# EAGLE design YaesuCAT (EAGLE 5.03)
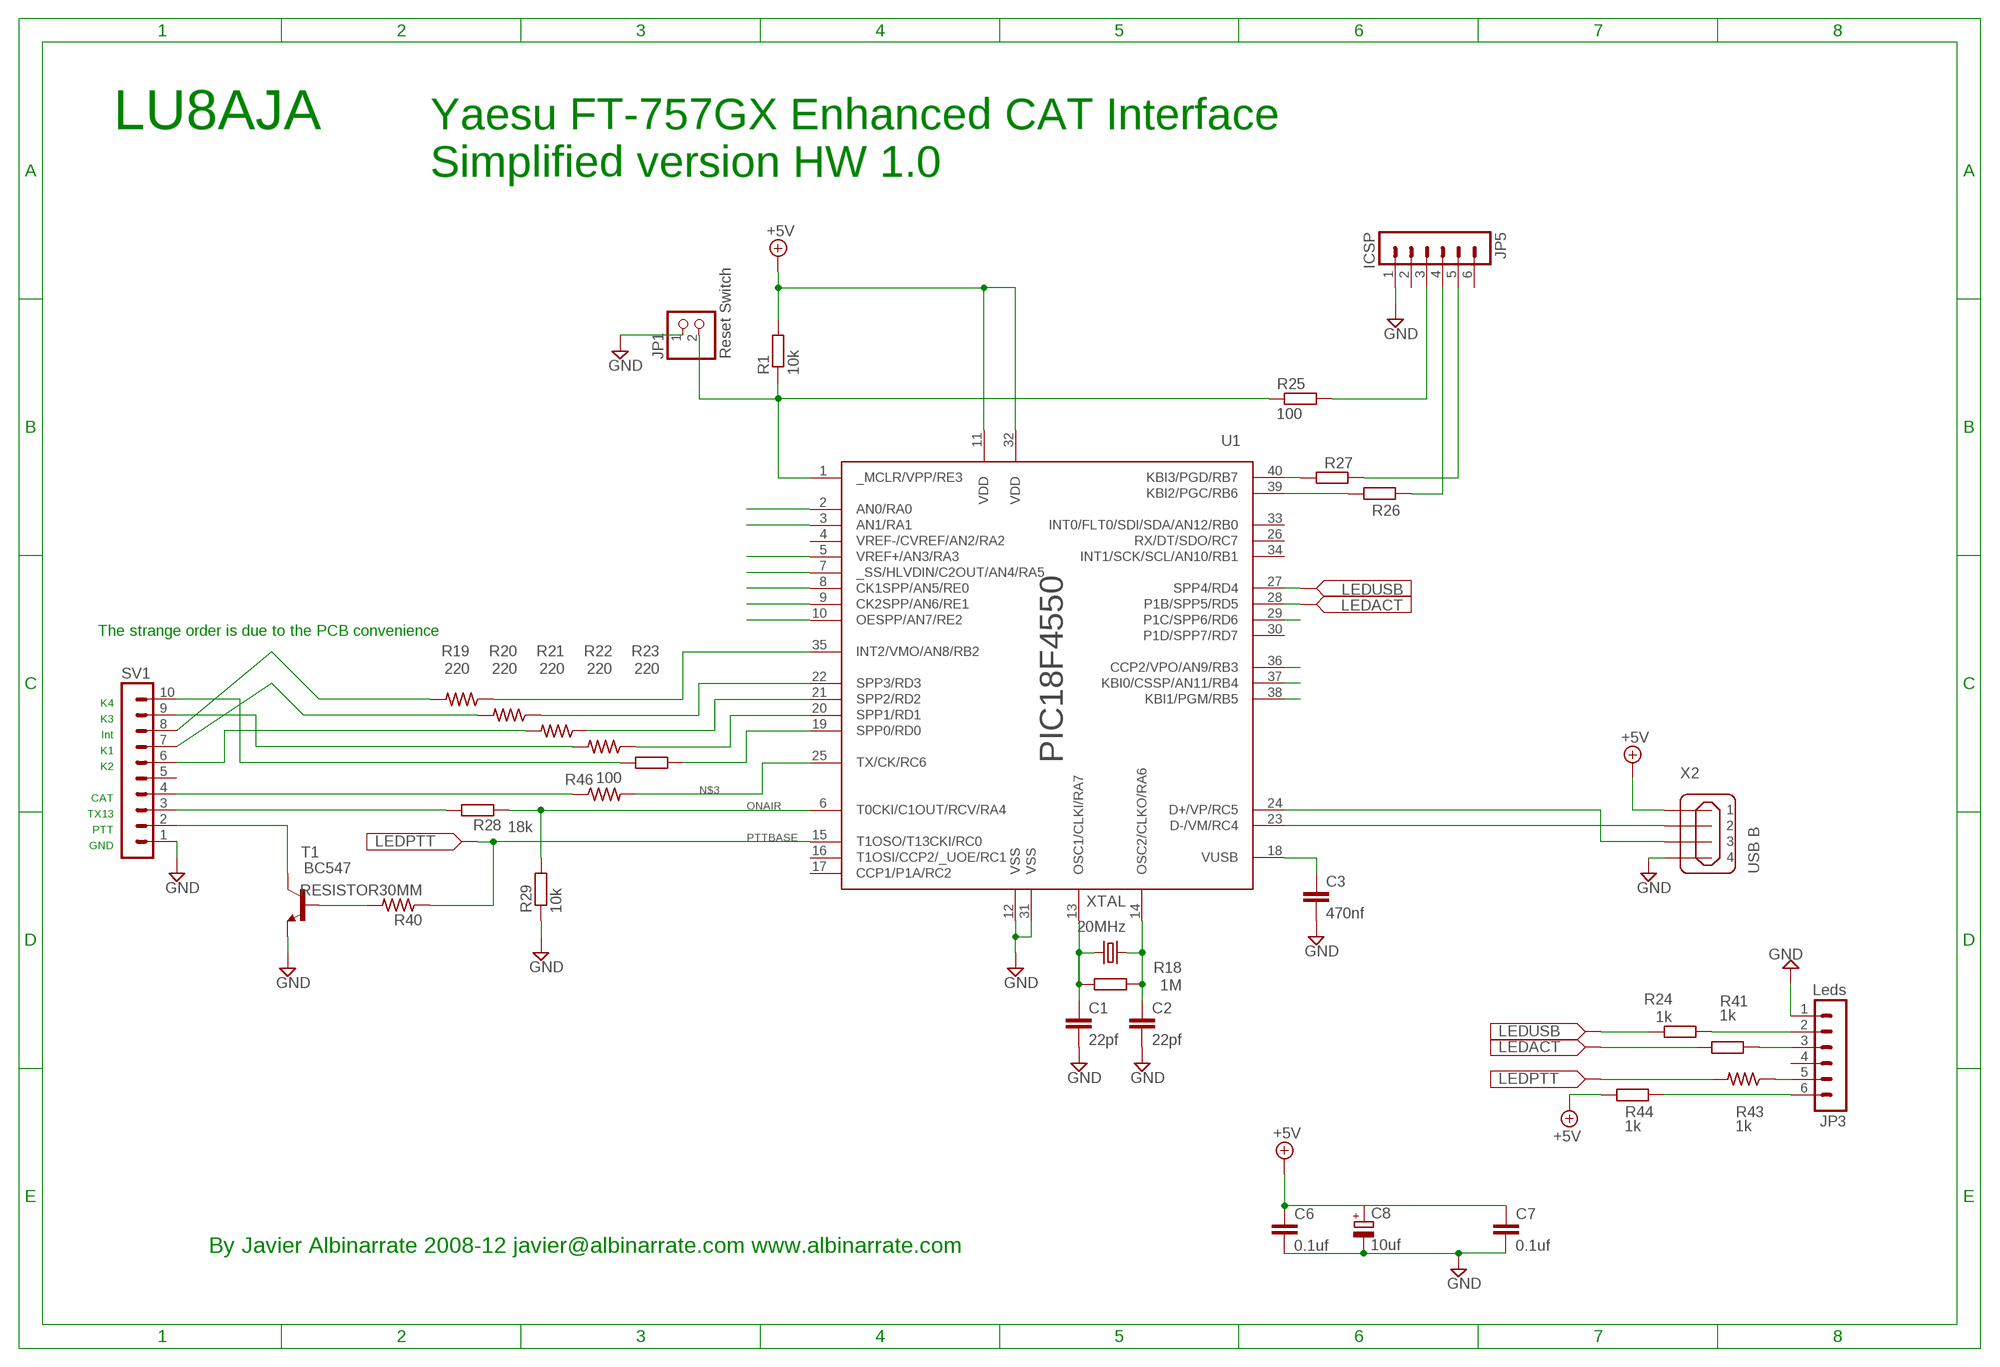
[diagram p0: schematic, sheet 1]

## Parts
C1  22pf  C-EU050-035X075  [C050-035X075]
C2  22pf  C-EU050-035X075  [C050-035X075]
C3  470nf  C-EU050-035X075  [C050-035X075]
C6  0.1uf  C-EU050-035X075  [C050-035X075]
C7  0.1uf  C-EU050-035X075  [C050-035X075]
C8  10uf  CPOL-EUE5-10.5  [E5-10,5]
JP1  Reset Switch  PINHD-1X2  [1X02]
JP3  Leds  MA06-1  [MA06-1]
JP5  ICSP  MA06-1  [MA06-1]
R1  10k  R-EU_0207/10  [0207/10]
R18  1M  R-EU_0207/10  [0207/10]
R19  220  R-US_0207/10  [0207/10]
R20  220  R-US_0207/10  [0207/10]
R21  220  R-US_0207/10  [0207/10]
R22  220  R-US_0207/10  [0207/10]
R23  220  R-EU_0207/10  [0207/10]
R24  1k  R-EU_0207/10  [0207/10]
R25  100  R-EU_0207/10  [0207/10]
R26  R-EU_0207/10  [0207/10]
R27  R-EU_0207/10  [0207/10]
R28  18k  R-EU_0207/10  [0207/10]
R29  10k  R-EU_0207/10  [0207/10]
R40  RESISTOR30MM  [R207/30MM]
R41  1k  R-EU_0207/10  [0207/10]
R43  1k  RESISTOR20MM  [R207/20MM]
R44  1k  R-EU_0207/10  [0207/10]
R46  100  R-US_0207/10  [0207/10]
SV1  MA10-1  [MA10-1]
T1  BC547  [TO92]
U1  PIC18F4550  [DIP40]
X2  USB B  MINI-USB_SHIELD4P-85-32004-00X  [85-32004-00X]
XTAL  20MHz  CRYSTALHC49U70  [HC49U70]

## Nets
+5V: C6.1 C7.1 C8.+ R1.2 R44.2 U1.11(VDD) U1.32(VDD) X2.1
AN0: U1.2(AN0/RA0)
AN1: U1.3(AN1/RA1)
AN3: U1.5(VREF+/AN3/RA3)
AN4: U1.7(_SS/HLVDIN/C2OUT/AN4/RA5)
AN5: U1.8(CK1SPP/AN5/RE0)
AN6: U1.9(CK2SPP/AN6/RE1)
AN7: U1.10(OESPP/AN7/RE2)
AN9: U1.36(CCP2/VPO/AN9/RB3)
D+: U1.24(D+/VP/RC5) X2.3
D-: U1.23(D-/VM/RC4) X2.2
GND: C1.2 C2.2 C3.2 C6.2 C7.2 C8.- JP1.1 JP3.1 JP5.1 R29.1 SV1.1 T1.1(E) U1.12(VSS) U1.31(VSS) X2.4
INT: R19.1 U1.35(INT2/VMO/AN8/RB2)
LEDACT: R41.1 U1.28(P1B/SPP5/RD5)
LEDUSB: R24.2 U1.27(SPP4/RD4)
N$1: JP1.2 R1.1 R25.1 U1.1(_MCLR/VPP/RE3)
N$2: JP5.4 R26.1
N$3: R46.2 U1.25(TX/CK/RC6)
N$4: R28.2 SV1.3
N$5: SV1.2 T1.3(C)
N$6: R46.1 SV1.4
N$7: R23.2 SV1.10
N$8: R22.2 SV1.9
N$9: R21.2 SV1.6
N$10: R20.1 U1.22(SPP3/RD3)
N$11: R27.2 U1.40(KBI3/PGD/RB7)
N$12: R26.2 U1.39(KBI2/PGC/RB6)
N$13: R21.1 U1.21(SPP2/RD2)
N$14: JP5.5 R27.1
N$15: R20.2 SV1.7
N$16: R19.2 SV1.8
N$20: JP5.3 R25.2
N$22: JP3.2 R24.1
N$23: JP3.3 R41.2
N$25: JP3.5 R43.P$1
N$30: JP3.6 R44.1
N$34: C1.1 R18.2 U1.13(OSC1/CLKI/RA7) XTAL.2
N$35: C2.1 R18.1 U1.14(OSC2/CLKO/RA6) XTAL.1
N$37: C3.1 U1.18(VUSB)
N$49: R40.P$2 T1.2(B)
ONAIR: R28.1 R29.2 U1.6(T0CKI/C1OUT/RCV/RA4)
PTTBASE: R40.P$1 R43.P$2 U1.15(T1OSO/T13CKI/RC0) ; supply symbol labelled LEDPTT
RD0: R23.1 U1.19(SPP0/RD0)
RD1: R22.1 U1.20(SPP1/RD1)
RESET: U1.29(P1C/SPP6/RD6)
START: U1.38(KBI1/PGM/RB5)
THRU: U1.37(KBI0/CSSP/AN11/RB4)
Unconnected: JP3.4 JP5.2 JP5.6 SV1.5 U1.4(VREF-/CVREF/AN2/RA2) U1.16(T1OSI/CCP2/_UOE/RC1) U1.17(CCP1/P1A/RC2) U1.26(RX/DT/SDO/RC7) U1.30(P1D/SPP7/RD7) U1.33(INT0/FLT0/SDI/SDA/AN12/RB0) U1.34(INT1/SCK/SCL/AN10/RB1) X2.M1(S1) X2.M2(S2)

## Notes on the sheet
- LU8AJA | Yaesu FT-757GX Enhanced CAT Interface
- Simplified version HW 1.0
- The strange order is due to the PCB convenience
- K4
- K3
- Int
- K1
- K2
- CAT
- TX13
- PTT
- GND
- By Javier Albinarrate 2008-12 javier@albinarrate.com www.albinarrate.com

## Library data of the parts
C1-C3 C6 C7 = resistor:C-EU: CAPACITOR, European symbol
C8 = resistor:CPOL-EU: POLARIZED CAPACITOR, European symbol
JP1 = pinhead:PINHD-1X2: PIN HEADER
JP3 JP5 = con-lstb:MA06-1: PIN HEADER
R1 R18 R23-R29 R41 R44 = resistor:R-EU_: RESISTOR, European symbol
R19-R22 R46 = resistor:R-US_: RESISTOR, American symbol
R40 R43 = components:RESISTOR
SV1 = con-lstb:MA10-1: PIN HEADER
T1 = transistor:BC547: NPN TRANSISTOR
U1 = components:PIC18F4550: PIC18F4550 DIP-40 Specially arranged for schematics for the Yaesu FT-757GX Enhanced CAT interface schematics.
X2 = con-cypressindustries:MINI-USB_SHIELD4P-: MINI USB 4 Pol. Source: www.cypressindustries.com
XTAL = crystal:CRYSTAL: CRYSTAL

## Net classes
0 default: width 0.508 mm, drill 0.127 mm, clearance 0.381 mm

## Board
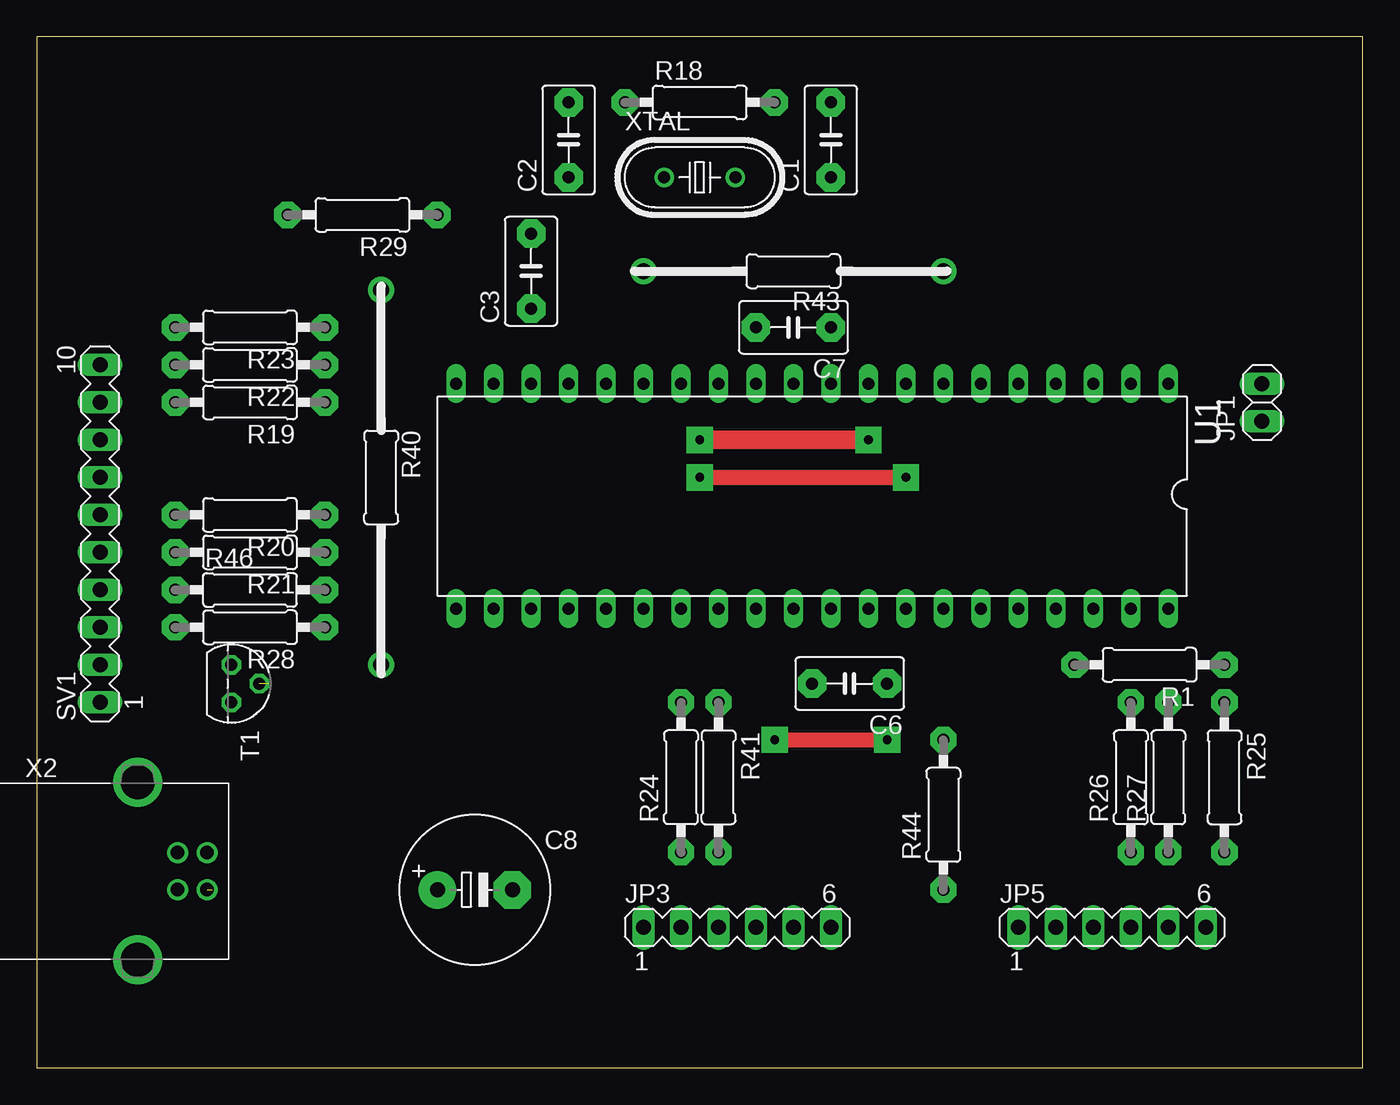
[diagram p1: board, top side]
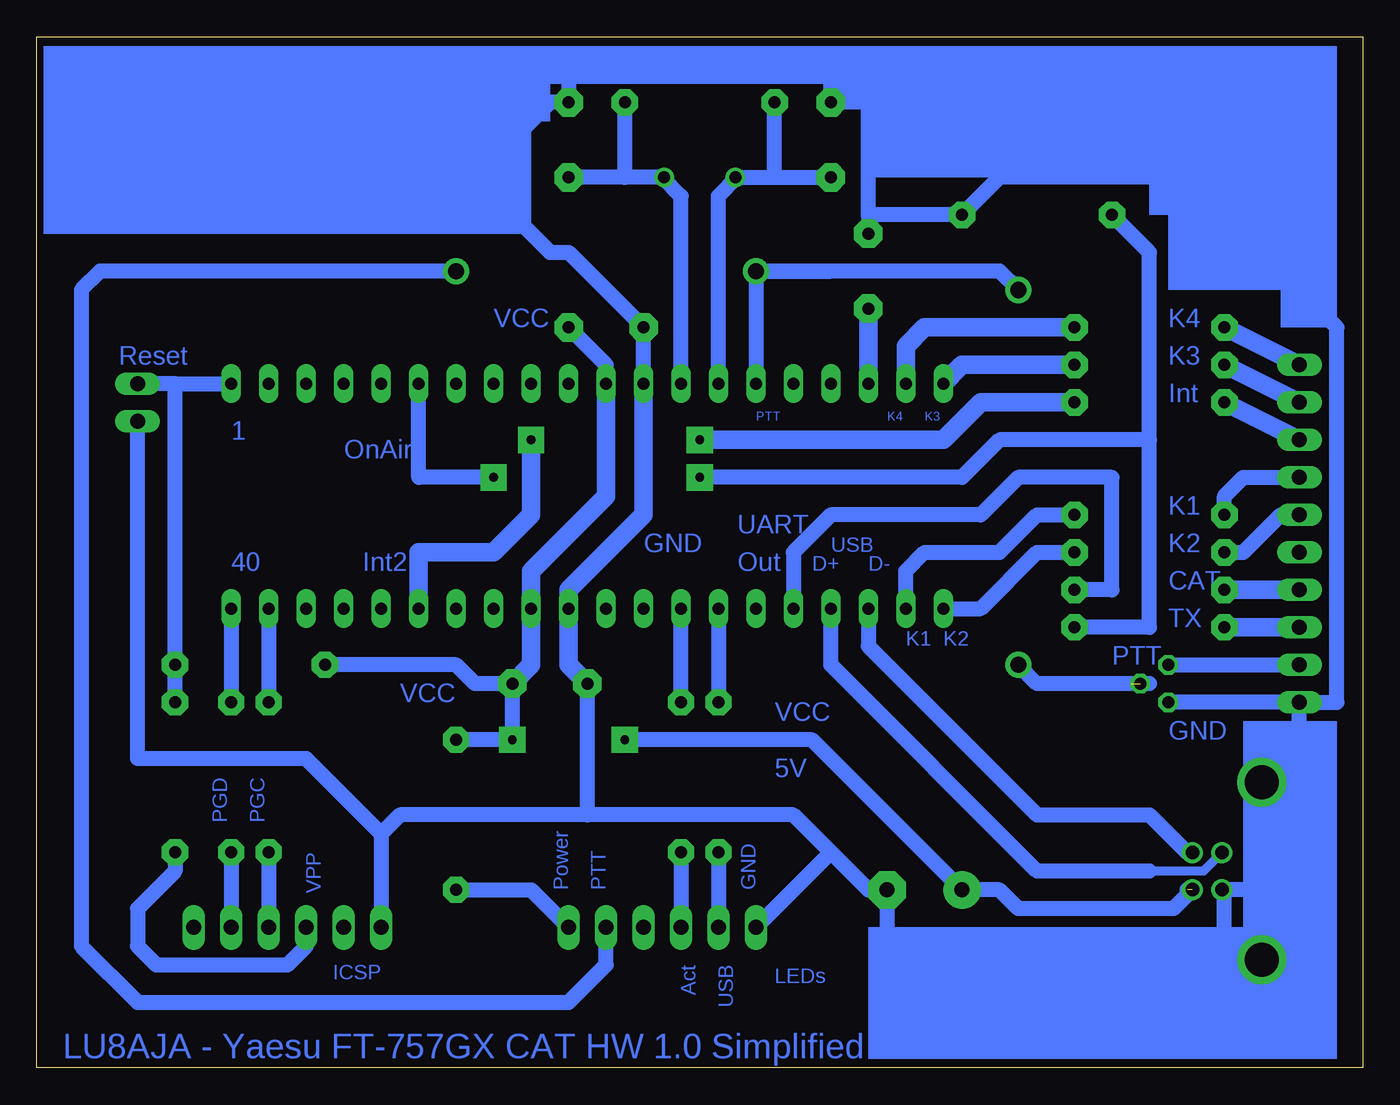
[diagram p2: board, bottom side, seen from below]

Size 89.84 x 69.84 mm. Coordinates in mm from the lower left corner, seen from the top.
Outline: 0,0 89.84,0 89.84,69.84 0,69.84 0,0
Copper layers (1*16): Top 0.035mm / dielectric 1.5mm / Bottom 0.035mm
Design rules "default": minimum track width 10mil, minimum drill 24mil, track to track 8mil, track to pad 8mil, pad to pad 8mil, via to via 8mil, smd to smd 8mil, copper to edge 40mil, drill to drill 8mil, minimum pad ring 10mil, minimum via ring 8mil, stop-mask expansion 4mil, vias tented up to drill 0mil, thermal gap 10mil

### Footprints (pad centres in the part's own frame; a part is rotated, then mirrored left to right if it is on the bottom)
C050-035X075 = drill 0.813 pad 1.93 octagon: 1 -2.54,0; 2 2.54,0
E5-10,5 = drill 1.016 pad 2.54 round: + -2.54,0 | drill 1.016 pad 2.54 octagon: - 2.54,0
1X02 = drill 1.016 long: 1 -1.27,0; 2 1.27,0
MA06-1 = drill 1.016 long: 1 -6.35,0; 2 -3.81,0; 3 -1.27,0; 4 1.27,0; 5 3.81,0; 6 6.35,0
0207/10 = drill 0.813 pad 1.778 octagon: 1 -5.08,0; 2 5.08,0
R207/30MM = drill 1.1 pad 1.778 round: P$1 -12.7,0; P$2 12.7,0
R207/20MM = drill 1.1 pad 1.778 round: P$1 -10.16,0; P$2 10.16,0
MA10-1 = drill 1.016 long: 1 -11.43,0; 2 -8.89,0; 3 -6.35,0; 4 -3.81,0; 5 -1.27,0; 6 1.27,0; 7 3.81,0; 8 6.35,0; 9 8.89,0; 10 11.43,0
TO92 = drill 0.813 octagon: 1 1.27,0; 2 0,1.905; 3 -1.27,0
DIP40 = drill 0.813 long: 1 -24.13,-8.89; 2 -21.59,-8.89; 3 -19.05,-8.89; 4 -16.51,-8.89; 5 -13.97,-8.89; 6 -11.43,-8.89; 7 -8.89,-8.89; 8 -6.35,-8.89; 9 -3.81,-8.89; 10 -1.27,-8.89; 11 1.27,-8.89; 12 3.81,-8.89; 13 6.35,-8.89; 14 8.89,-8.89; 15 11.43,-8.89; 16 13.97,-8.89; 17 16.51,-8.89; 18 19.05,-8.89; 19 21.59,-8.89; 20 24.13,-8.89; 21 24.13,6.35; 22 21.59,6.35; 23 19.05,6.35; 24 16.51,6.35; 25 13.97,6.35; 26 11.43,6.35; 27 8.89,6.35; 28 6.35,6.35; 29 3.81,6.35; 30 1.27,6.35; 31 -1.27,6.35; 32 -3.81,6.35; 33 -6.35,6.35; 34 -8.89,6.35; 35 -11.43,6.35; 36 -13.97,6.35; 37 -16.51,6.35; 38 -19.05,6.35; 39 -21.59,6.35; 40 -24.13,6.35
85-32004-00X = drill 0.92 pad 1.27 round: 1 4.71,-1.25; 2 4.71,1.25; 3 2.71,1.25; 4 2.71,-1.25 | drill 2.3 pad 3 round: M1 0,6.02; M2 0,-6.02
HC49U70 = drill 0.813 round: 1 -2.413,0; 2 2.413,0

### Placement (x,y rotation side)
C1  53.81,62.86 90 top
C2  36.03,62.86 90 top
C3  33.49,53.97 90 top
C6  55.08,26.03 180 top
C7  51.27,50.16 180 top
C8  29.68,12.06 0 top
JP1  83.02,45.08 90 top
JP3  47.46,9.52 0 top
JP5  72.86,9.52 0 top
R1  75.4,27.3 180 top
R18  44.92,65.4 0 top
R19  14.44,45.08 180 top
R20  14.44,37.46 180 top
R21  14.44,34.92 180 top
R22  14.44,47.62 180 top
R23  14.44,50.16 180 top
R24  43.65,19.68 90 top
R25  80.48,19.68 270 top
R26  74.13,19.68 90 top
R27  76.67,19.68 90 top
R28  14.44,29.84 180 top
R29  22.06,57.78 180 top
R40  23.33,40 270 top
R41  46.19,19.68 270 top
R43  51.27,53.97 180 top
R44  61.43,17.14 90 top
R46  14.44,32.38 0 top
SV1  4.28,36.19 90 top
T1  13.17,26.03 270 top
U1  52.54,37.46 180 top
X2  6.82,13.33 0 top
XTAL  44.92,60.32 0 top

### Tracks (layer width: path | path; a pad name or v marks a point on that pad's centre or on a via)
+5V  (via drill 0.6 pad 1.78)  (1 unrouted)
  Top 1.016: v50,22.22 v57.62,22.22
  Bottom 1.016: U1.11 51.27,47.62 C7.1 | 11.88,12.08 11.9,12.06 | R1.2 61.43,27.3 60.16,26.03 C6.1 v57.62,22.22 R44.2 | v50,22.22 37.3,22.22 C8.+ 24.6,12.06 23.33,10.79 12.82,10.79 X2.1
  Bottom 1.27: U1.11 51.27,38.73 56.35,33.65 U1.32 56.35,27.3 C6.1
D+
  Bottom 0.61: X2.3 10.78,13.33 14.44,13.33
  Bottom 1.016: 14.44,13.33 22.06,13.33 36.03,27.3 U1.24
D-
  Bottom 1.016: U1.23 33.49,28.57 22.06,17.14 14.44,17.14 11.88,14.58 X2.2
GND
  Bottom 1.016: SV1.1 T1.1 | 33.49,57.78 C3.2 | 33.49,57.78 33.49,65.4 C2.2 36.03,67.94 53.81,67.94 C1.2 55.08,65.4 57.62,62.86 57.62,57.78 55.08,55.24 53.81,55.24 C7.2 U1.12 | 33.49,57.78 R29.1 24.6,60.32 11.9,60.32 1.74,50.16 1.74,24.76 SV1.1 | X2.4 5.53,12.08 4.28,13.33 SV1.1 | 66.51,15.87 JP5.1 | 66.51,15.87 65.24,17.14 52.54,17.14 | 52.54,17.14 C6.2 | 36.03,14.6 33.49,12.06 C8.- 32.22,8.25 9.36,8.25 9.36,12.06 | 36.03,14.6 38.57,17.14 52.54,17.14 | JP1.1 83.02,20.95 71.59,20.95 66.51,15.87 | 36.03,14.6 JP3.1
  Bottom 1.27: U1.12 48.73,37.46 53.81,32.38 U1.31 53.81,27.3 C6.2
INT  (via drill 0.6 pad 1.78)
  Top 1.27: v56.35,42.54 v44.92,42.54
  Bottom 1.27: R19.1 25.87,45.08 28.41,42.54 v44.92,42.54 | U1.35 63.97,34.92 58.89,34.92 56.35,37.46 v56.35,42.54
LEDACT
  Bottom 1.016: R41.1 U1.28
LEDUSB
  Bottom 1.016: U1.27 R24.2
N$1
  Bottom 1.016: 80.48,46.35 R1.1 R25.1 | 80.48,46.35 U1.1 | 80.48,46.35 JP1.2
N$2
  Bottom 1.016: R26.1 JP5.4
N$3
  Bottom 1.016: R46.2 16.98,32.38 16.98,40 23.33,40 25.87,37.46 36.03,37.46 38.57,34.92 U1.25
N$4
  Bottom 1.27: R28.2 SV1.3
N$5
  Bottom 1.016: T1.3 SV1.2
N$6
  Bottom 1.27: R46.1 SV1.4
N$7
  Bottom 1.27: R23.2 SV1.10
N$8
  Bottom 1.27: R22.2 SV1.9
N$9
  Bottom 1.016: R21.2 8.09,34.92 5.55,37.46 SV1.6
N$10
  Bottom 1.016: U1.22 30.95,33.65 29.68,34.92 24.6,34.92 22.06,37.46 R20.1
N$11
  Bottom 1.016: U1.40 R27.2
N$12
  Bottom 1.016: U1.39 R26.2
N$13
  Bottom 1.016: U1.21 25.87,31.11 22.06,34.92 R21.1
N$14
  Bottom 1.016: R27.1 JP5.5
N$15
  Bottom 1.016: R20.2 9.36,38.73 8.09,40 SV1.7
N$16
  Bottom 1.27: R19.2 SV1.8
N$20
  Bottom 1.016: R25.2 80.48,13.33 83.02,10.79 83.02,8.25 81.75,6.98 72.86,6.98 71.59,8.25 JP5.3
N$22
  Bottom 1.016: R24.1 JP3.2
N$23
  Bottom 1.016: R41.2 JP3.3
N$25
  Bottom 1.016: R43.P$1 85.56,53.97 86.83,52.7 86.83,8.25 83.02,4.44 53.81,4.44 51.27,6.98 JP3.5
N$30
  Bottom 1.016: R44.1 56.35,12.06 JP3.6
N$34
  Bottom 1.016: U1.13 46.19,59.05 47.46,60.32 XTAL.2 50,60.32 | 50,60.32 C1.1 | 50,60.32 R18.2
N$35
  Bottom 1.016: U1.14 43.65,59.05 42.38,60.32 XTAL.1 39.84,60.32 | 39.84,60.32 C2.1 | 39.84,60.32 R18.1
N$37
  Bottom 1.27: U1.18 C3.1
N$49  (1 unrouted)
  Bottom 1.016: R40.P$2 22.06,26.03 15.71,26.03 14.44,26.03
ONAIR  (via drill 0.6 pad 1.78)
  Top 1.016: v44.92,40 v58.89,40
  Bottom 1.016: R28.1 14.44,29.84 14.44,42.54 | 14.44,42.54 24.6,42.54 27.14,40 v44.92,40 | v58.89,40 63.97,40 U1.6 | R29.2 14.44,55.24 14.44,42.54
PTTBASE
  Bottom 1.016: R40.P$1 24.6,53.97 R43.P$2 | R43.P$2 36.03,53.97 | R43.P$2 U1.15
RD0
  Bottom 1.27: R23.1 29.68,50.16 30.95,48.89 U1.19
RD1
  Bottom 1.27: R22.1 27.14,47.62 U1.20
(copper drawn outside any net)
  shapes: Bottom area x12

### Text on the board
Bottom: K4 | VCC | K3 | Reset | Int | K3 | K4 | PTT | 1 | OnAir | K1 | UART | K2 | USB | GND | D- | D+ | Out | Int2 | 40 | CAT | TX | K2 | K1 | PTT | VCC | VCC | GND | 5V | PGC | PGD | VPP | GND | PTT | Power | USB | Act | ICSP | LEDs | LU8AJA - Yaesu FT-757GX CAT HW 1.0 Simplified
